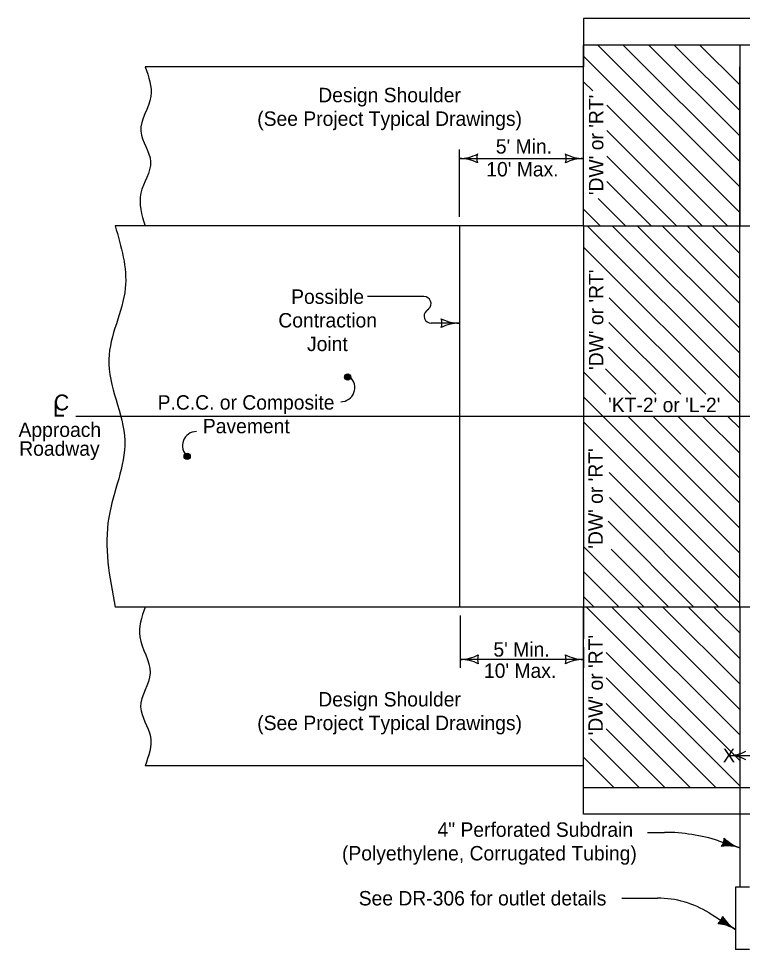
# Model space of a CAD drawing. Extents: x 10045 to 81668, y 6370 to 11018.
# Drawn here: x 10045 to 10888, y 6421 to 7505 of the extents above; entities that cross this region are included whole.
import ezdxf

# ---------------------------------------------------------------- set-up
doc = ezdxf.new("R2010")
doc.units = 0
for name, color, linetype in [('Alignment', 7, 'Continuous'), ('Default', 7, 'Continuous'), ('dsnStdLineWork', 7, 'Continuous')]:
    doc.layers.add(name, color=color, linetype=linetype)

msp = doc.modelspace()

# ---------------------------------------------------------------- linework, layer by layer
at = {"layer": 'Alignment'}
for p, q in [((10558.7, 7274.2), (10558.7, 7352.6)), ((10558.7, 7274.2), (10558.7, 7352.6)), ((10703.2, 7311.2), (10703.2, 7352.6)), ((10703.2, 7311.2), (10703.2, 7352.6)), ((10558.7, 7342.4), (10703.2, 7342.4)), ((10558.7, 7342.4), (10703.2, 7342.4)), ((10703.2, 7263.9), (10703.2, 6819.8)), ((10703.2, 7263.9), (10703.2, 6819.8)), ((10517.3, 7181.6), (10451.7, 7181.6)), ((10517.3, 7181.6), (10451.7, 7181.6)), ((10521.5, 7166.1), (10522.8, 7167.2)), ((10521.5, 7166.1), (10522.8, 7167.2)), ((10558.4, 7150.5), (10525.7, 7150.5)), ((10558.4, 7150.5), (10525.7, 7150.5)), ((10333.1, 7041.9), (10333.1, 7041.9)), ((10333.1, 7041.9), (10333.1, 7041.9)), ((12067.5, 6819.8), (10703.2, 6819.8)), ((12067.5, 6819.8), (10703.2, 6819.8)), ((10559.6, 6810.2), (10559.6, 6749.3)), ((10559.6, 6810.2), (10559.6, 6749.3)), ((10703.2, 6773.2), (10703.2, 6749.3)), ((10703.2, 6773.2), (10703.2, 6749.3)), ((10703.2, 6758.9), (10559.6, 6758.9)), ((10703.2, 6758.9), (10559.6, 6758.9)), ((10872.2, 6647.1), (10903.5, 6647.1)), ((10872.2, 6647.1), (10903.5, 6647.1)), ((10777.8, 6557.4), (10797.5, 6557.4)), ((10777.8, 6557.4), (10797.5, 6557.4)), ((10747.8, 6480.8), (10789.3, 6480.8)), ((10747.8, 6480.8), (10789.3, 6480.8)), ((10849.4, 6463.6), (10880, 6444.4)), ((10849.4, 6463.6), (10880, 6444.4))]:
    msp.add_line(p, q, dxfattribs=at)
for centre, radius, start, end in [((10517.3, 7173.4), 8.22, 311.3092, 90), ((10517.3, 7173.4), 8.22, 311.3092, 90), ((10525.7, 7158.8), 8.22, 131.309, 270), ((10525.7, 7158.8), 8.22, 131.309, 270), ((10420.4, 7075.4), 16.4, 270, 48.6908), ((10420.4, 7075.4), 16.4, 270, 48.6908), ((10252.4, 7007.9), 16.4, 90, 228.691), ((10252.4, 7007.9), 16.4, 90, 228.691), ((10797.5, 6351.9), 205.6, 72.1406, 90), ((10797.5, 6351.9), 205.6, 72.1406, 90), ((10789.3, 6367.8), 113.1, 57.9168, 90), ((10789.3, 6367.8), 113.1, 57.9168, 90)]:
    msp.add_arc(centre, radius, start, end, dxfattribs=at)
at = {"layer": 'Default'}
msp.add_line((11628.3, 7474.4), (10703.2, 7474.4), dxfattribs=at)
msp.add_line((11628.3, 7474.4), (10703.2, 7474.4), dxfattribs=at)
at = {"layer": 'dsnStdLineWork'}
for p, q in [((11591.3, 7505.2), (10703.2, 7505.2)), ((10703.2, 7505.2), (10703.2, 7448.9)), ((11591.3, 7505.2), (10703.2, 7505.2)), ((10703.2, 7505.2), (10703.2, 7448.9)), ((10703.2, 7263.9), (10703.2, 7474.4)), ((10703.2, 7263.9), (10703.2, 7474.4)), ((10885.1, 7309.1), (10719.8, 7474.4)), ((10885.1, 7309.1), (10719.8, 7474.4)), ((10885.1, 7338.8), (10749.5, 7474.4)), ((10885.1, 7338.8), (10749.5, 7474.4)), ((10885.1, 7368.5), (10779.2, 7474.4)), ((10885.1, 7368.5), (10779.2, 7474.4)), ((10885.1, 7398.2), (10808.9, 7474.4)), ((10885.1, 7398.2), (10808.9, 7474.4)), ((10885.1, 7427.9), (10838.6, 7474.4)), ((10885.1, 7427.9), (10838.6, 7474.4)), ((10885.1, 7474.4), (10885.1, 7263.9)), ((10885.1, 7474.4), (10885.1, 7263.9)), ((10885.1, 7279.4), (10703.2, 7461.3)), ((10885.1, 7279.4), (10703.2, 7461.3)), ((10703.2, 7448.9), (10192.4, 7448.9)), ((10703.2, 7448.9), (10192.4, 7448.9)), ((10703.2, 7263.9), (10703.2, 7448.9)), ((10703.2, 7263.9), (10703.2, 7448.9)), ((10885.1, 7263.9), (10885.1, 7448.9)), ((10885.1, 7263.9), (10885.1, 7448.9)), ((10713.8, 7421), (10703.2, 7431.6)), ((10713.8, 7421), (10703.2, 7431.6)), ((10870.9, 7263.9), (10730.2, 7404.5)), ((10870.9, 7263.9), (10730.2, 7404.5)), ((10841.2, 7263.9), (10730.2, 7374.8)), ((10841.2, 7263.9), (10730.2, 7374.8)), ((10811.5, 7263.9), (10730.2, 7345.1)), ((10811.5, 7263.9), (10730.2, 7345.1)), ((10781.8, 7263.9), (10730.2, 7315.4)), ((10781.8, 7263.9), (10730.2, 7315.4)), ((10703.2, 7263.9), (10703.2, 7300.9)), ((10703.2, 7263.9), (10703.2, 7300.9)), ((10752.1, 7263.9), (10720.3, 7295.6)), ((10752.1, 7263.9), (10720.3, 7295.6)), ((10722.4, 7263.9), (10703.2, 7283.1)), ((10722.4, 7263.9), (10703.2, 7283.1)), ((10703.2, 7263.9), (10157.6, 7263.9)), ((10703.2, 7263.9), (10157.6, 7263.9)), ((10558.7, 7263.9), (10558.7, 6819.8)), ((10558.7, 7263.9), (10558.7, 6819.8)), ((10703.2, 7263.9), (12114.2, 7263.9)), ((10703.2, 7263.9), (12114.2, 7263.9)), ((10885.1, 7086.3), (10707.5, 7263.9)), ((10885.1, 7086.3), (10707.5, 7263.9)), ((10885.1, 7115.4), (10736.6, 7263.9)), ((10885.1, 7115.4), (10736.6, 7263.9)), ((10885.1, 7144.5), (10765.7, 7263.9)), ((10885.1, 7144.5), (10765.7, 7263.9)), ((10885.1, 7173.5), (10794.8, 7263.9)), ((10885.1, 7173.5), (10794.8, 7263.9)), ((10885.1, 7202.6), (10823.8, 7263.9)), ((10885.1, 7202.6), (10823.8, 7263.9)), ((10885.1, 7231.7), (10852.9, 7263.9)), ((10885.1, 7231.7), (10852.9, 7263.9)), ((10885.1, 6819.8), (10885.1, 7263.9)), ((10885.1, 6819.8), (10885.1, 7263.9)), ((10885.1, 7057.2), (10703.2, 7239.2)), ((10885.1, 7057.2), (10703.2, 7239.2)), ((10845.6, 7067.7), (10733.1, 7180.2)), ((10845.6, 7067.7), (10733.1, 7180.2)), ((10520.2, 7164.9), (10521.5, 7166.1)), ((10520.2, 7164.9), (10521.5, 7166.1)), ((10816.5, 7067.7), (10732.8, 7151.4)), ((10816.5, 7067.7), (10732.8, 7151.4)), ((10787.4, 7067.7), (10732.4, 7122.7)), ((10787.4, 7067.7), (10732.4, 7122.7)), ((10729.3, 7067.7), (10703.2, 7093.8)), ((10729.3, 7067.7), (10703.2, 7093.8)), ((10758.3, 7067.7), (10728.8, 7097.3)), ((10758.3, 7067.7), (10728.8, 7097.3)), ((10885.1, 6882.8), (10703.2, 7064.7)), ((10885.1, 6882.8), (10703.2, 7064.7)), ((11628.3, 7041.9), (10112, 7041.9)), ((11628.3, 7041.9), (10112, 7041.9)), ((10885.1, 6853.7), (10703.2, 7035.7)), ((10885.1, 6853.7), (10703.2, 7035.7)), ((10885.1, 6911.9), (10755.1, 7041.9)), ((10885.1, 6911.9), (10755.1, 7041.9)), ((10885.1, 6940.9), (10784.2, 7041.9)), ((10885.1, 6940.9), (10784.2, 7041.9)), ((10885.1, 6970), (10813.3, 7041.9)), ((10885.1, 6970), (10813.3, 7041.9)), ((10885.1, 6999.1), (10842.3, 7041.9)), ((10885.1, 6999.1), (10842.3, 7041.9)), ((10885.1, 7028.2), (10871.4, 7041.9)), ((10885.1, 7028.2), (10871.4, 7041.9)), ((10885.1, 6824.6), (10733.1, 6976.6)), ((10885.1, 6824.6), (10733.1, 6976.6)), ((10860.9, 6819.8), (10733.4, 6947.3)), ((10860.9, 6819.8), (10733.4, 6947.3)), ((10831.8, 6819.8), (10731.7, 6919.9)), ((10831.8, 6819.8), (10731.7, 6919.9)), ((10773.6, 6819.8), (10703.2, 6890.3)), ((10773.6, 6819.8), (10703.2, 6890.3)), ((10802.7, 6819.8), (10735.3, 6887.2)), ((10802.7, 6819.8), (10735.3, 6887.2)), ((10744.6, 6819.8), (10703.2, 6861.2)), ((10744.6, 6819.8), (10703.2, 6861.2)), ((10715.5, 6819.8), (10703.2, 6832.1)), ((10715.5, 6819.8), (10703.2, 6832.1)), ((10703.2, 6819.8), (10157.6, 6819.8)), ((10703.2, 6819.8), (10157.6, 6819.8)), ((10703.2, 6819.8), (10703.2, 6782.8)), ((10703.2, 6634.8), (10703.2, 6819.8)), ((10703.2, 6609.3), (10703.2, 6819.8)), ((10703.2, 6819.8), (10703.2, 6782.8)), ((10703.2, 6634.8), (10703.2, 6819.8)), ((10703.2, 6609.3), (10703.2, 6819.8)), ((10885.1, 6641.2), (10706.5, 6819.8)), ((10885.1, 6641.2), (10706.5, 6819.8)), ((10885.1, 6670.9), (10736.2, 6819.8)), ((10885.1, 6670.9), (10736.2, 6819.8)), ((10885.1, 6700.6), (10765.9, 6819.8)), ((10885.1, 6700.6), (10765.9, 6819.8)), ((10885.1, 6730.3), (10795.6, 6819.8)), ((10885.1, 6730.3), (10795.6, 6819.8)), ((10885.1, 6760), (10825.3, 6819.8)), ((10885.1, 6760), (10825.3, 6819.8)), ((10885.1, 6789.7), (10855, 6819.8)), ((10885.1, 6789.7), (10855, 6819.8)), ((10885.1, 6819.4), (10884.7, 6819.8)), ((10885.1, 6819.4), (10884.7, 6819.8)), ((10885.1, 6819.8), (10885.1, 6609.3)), ((10885.1, 6819.8), (10885.1, 6609.3)), ((10885.1, 6611.5), (10729.6, 6767)), ((10885.1, 6611.5), (10729.6, 6767)), ((10857.6, 6609.3), (10729.6, 6737.3)), ((10857.6, 6609.3), (10729.6, 6737.3)), ((10827.9, 6609.3), (10729.6, 6707.6)), ((10827.9, 6609.3), (10729.6, 6707.6)), ((10798.2, 6609.3), (10729.6, 6677.9)), ((10798.2, 6609.3), (10729.6, 6677.9)), ((10768.5, 6609.3), (10711.3, 6666.5)), ((10768.5, 6609.3), (10711.3, 6666.5)), ((10738.8, 6609.3), (10703.2, 6645)), ((10738.8, 6609.3), (10703.2, 6645)), ((10703.2, 6634.8), (10192.4, 6634.8)), ((10703.2, 6634.8), (10192.4, 6634.8)), ((10703.2, 6578.5), (10703.2, 6634.8)), ((10703.2, 6578.5), (10703.2, 6634.8)), ((11628.3, 6609.3), (10703.2, 6609.3)), ((11628.3, 6609.3), (10703.2, 6609.3)), ((10885.1, 6609.3), (10885.1, 6493.6)), ((10885.1, 6609.3), (10885.1, 6493.6)), ((11591.3, 6578.5), (10703.2, 6578.5)), ((11591.3, 6578.5), (10703.2, 6578.5)), ((10860.5, 6547.5), (10885.1, 6539.6)), ((10860.5, 6547.5), (10885.1, 6539.6)), ((10885.1, 6539.6), (10866.3, 6545.7)), ((10885.1, 6539.6), (10866.3, 6545.7)), ((10896.4, 6493.6), (10880, 6493.6)), ((10880, 6493.6), (10880, 6421.2)), ((10896.4, 6493.6), (10880, 6493.6)), ((10880, 6493.6), (10880, 6421.2)), ((10880, 6444.4), (10863.2, 6454.9)), ((10880, 6444.4), (10863.2, 6454.9)), ((10896.4, 6421.2), (10880, 6421.2)), ((10896.4, 6421.2), (10880, 6421.2))]:
    msp.add_line(p, q, dxfattribs=at)
for points in [[(10885.1, 7263.9), (10885.1, 7263.9)], [(10885.1, 7263.9), (10885.1, 7263.9)], [(10428.8, 7084.5), (10427.6, 7085), (10425.7, 7085.6), (10425.4, 7087.5), (10425.6, 7089.2), (10426.8, 7090.8), (10428.6, 7090.6), (10430.5, 7090.4), (10431.4, 7088.8), (10431.6, 7087.3), (10430.5, 7085.2), (10429.1, 7085), (10427.2, 7085.5), (10425.7, 7086.7), (10425.7, 7088.5), (10426.9, 7089.9), (10428.6, 7090.1), (10430.5, 7089.7), (10430.8, 7088.7), (10431.2, 7087.4), (10430.3, 7085.8), (10428.9, 7085.9), (10427.3, 7086.1), (10426.2, 7087), (10426.8, 7088.6), (10428, 7089.5), (10429.5, 7089.5), (10429.9, 7088.7), (10430.4, 7087.7), (10429.7, 7086.5), (10428.5, 7086.2), (10427.5, 7086.7), (10427.4, 7087.9), (10427.9, 7088.7), (10429, 7089), (10429.5, 7088.6), (10429.8, 7087.9), (10429.3, 7087), (10428.5, 7086.8), (10427.8, 7087.3), (10427.9, 7087.9), (10428.4, 7088.3), (10429.2, 7088.3), (10429.2, 7087.7), (10428.5, 7087.4)], [(10428.8, 7084.5), (10427.6, 7085), (10425.7, 7085.6), (10425.4, 7087.5), (10425.6, 7089.2), (10426.8, 7090.8), (10428.6, 7090.6), (10430.5, 7090.4), (10431.4, 7088.8), (10431.6, 7087.3), (10430.5, 7085.2), (10429.1, 7085), (10427.2, 7085.5), (10425.7, 7086.7), (10425.7, 7088.5), (10426.9, 7089.9), (10428.6, 7090.1), (10430.5, 7089.7), (10430.8, 7088.7), (10431.2, 7087.4), (10430.3, 7085.8), (10428.9, 7085.9), (10427.3, 7086.1), (10426.2, 7087), (10426.8, 7088.6), (10428, 7089.5), (10429.5, 7089.5), (10429.9, 7088.7), (10430.4, 7087.7), (10429.7, 7086.5), (10428.5, 7086.2), (10427.5, 7086.7), (10427.4, 7087.9), (10427.9, 7088.7), (10429, 7089), (10429.5, 7088.6), (10429.8, 7087.9), (10429.3, 7087), (10428.5, 7086.8), (10427.8, 7087.3), (10427.9, 7087.9), (10428.4, 7088.3), (10429.2, 7088.3), (10429.2, 7087.7), (10428.5, 7087.4)], [(10241.8, 6992.2), (10240.6, 6992.8), (10238.7, 6993.4), (10238.3, 6995.3), (10238.6, 6997), (10239.8, 6998.5), (10241.6, 6998.4), (10243.5, 6998.1), (10244.4, 6996.6), (10244.5, 6995), (10243.4, 6992.9), (10242, 6992.7), (10240.2, 6993.2), (10238.6, 6994.4), (10238.6, 6996.2), (10239.9, 6997.7), (10241.6, 6997.8), (10243.4, 6997.5), (10243.7, 6996.4), (10244.1, 6995.1), (10243.2, 6993.5), (10241.9, 6993.6), (10240.3, 6993.8), (10239.1, 6994.7), (10239.7, 6996.3), (10240.9, 6997.2), (10242.5, 6997.3), (10242.9, 6996.4), (10243.4, 6995.5), (10242.6, 6994.2), (10241.4, 6993.9), (10240.4, 6994.5), (10240.3, 6995.6), (10240.9, 6996.5), (10241.9, 6996.8), (10242.5, 6996.3), (10242.8, 6995.7), (10242.2, 6994.7), (10241.5, 6994.6), (10240.7, 6995), (10240.9, 6995.6), (10241.4, 6996), (10242.1, 6996), (10242.1, 6995.5), (10241.5, 6995.2)], [(10241.8, 6992.2), (10240.6, 6992.8), (10238.7, 6993.4), (10238.3, 6995.3), (10238.6, 6997), (10239.8, 6998.5), (10241.6, 6998.4), (10243.5, 6998.1), (10244.4, 6996.6), (10244.5, 6995), (10243.4, 6992.9), (10242, 6992.7), (10240.2, 6993.2), (10238.6, 6994.4), (10238.6, 6996.2), (10239.9, 6997.7), (10241.6, 6997.8), (10243.4, 6997.5), (10243.7, 6996.4), (10244.1, 6995.1), (10243.2, 6993.5), (10241.9, 6993.6), (10240.3, 6993.8), (10239.1, 6994.7), (10239.7, 6996.3), (10240.9, 6997.2), (10242.5, 6997.3), (10242.9, 6996.4), (10243.4, 6995.5), (10242.6, 6994.2), (10241.4, 6993.9), (10240.4, 6994.5), (10240.3, 6995.6), (10240.9, 6996.5), (10241.9, 6996.8), (10242.5, 6996.3), (10242.8, 6995.7), (10242.2, 6994.7), (10241.5, 6994.6), (10240.7, 6995), (10240.9, 6995.6), (10241.4, 6996), (10242.1, 6996), (10242.1, 6995.5), (10241.5, 6995.2)], [(10865.6, 6542.1), (10867.4, 6545.3), (10867.8, 6549.1), (10871.3, 6545.7), (10877.5, 6542.1), (10869.8, 6542.7), (10866.3, 6542.3), (10868, 6545.1), (10868.5, 6547.5), (10870.8, 6545.3), (10874.2, 6543.1), (10869.9, 6543.3), (10867.6, 6543.2), (10869, 6546.1), (10871.3, 6544.1), (10869, 6544.1), (10869.3, 6545.1), (10870.2, 6544.5)], [(10865.6, 6542.1), (10867.4, 6545.3), (10867.8, 6549.1), (10871.3, 6545.7), (10877.5, 6542.1), (10869.8, 6542.7), (10866.3, 6542.3), (10868, 6545.1), (10868.5, 6547.5), (10870.8, 6545.3), (10874.2, 6543.1), (10869.9, 6543.3), (10867.6, 6543.2), (10869, 6546.1), (10871.3, 6544.1), (10869, 6544.1), (10869.3, 6545.1), (10870.2, 6544.5)], [(10861.6, 6451.6), (10864.2, 6454.3), (10865.5, 6457.9), (10868.1, 6453.7), (10873.2, 6448.6), (10865.9, 6451.2), (10862.4, 6451.6), (10864.8, 6453.9), (10865.8, 6456.1), (10867.5, 6453.4), (10870.3, 6450.5), (10866.1, 6451.7), (10863.9, 6452.2), (10865.9, 6454.7), (10867.7, 6452.1), (10865.4, 6452.7), (10866, 6453.6), (10866.7, 6452.8)], [(10861.6, 6451.6), (10864.2, 6454.3), (10865.5, 6457.9), (10868.1, 6453.7), (10873.2, 6448.6), (10865.9, 6451.2), (10862.4, 6451.6), (10864.8, 6453.9), (10865.8, 6456.1), (10867.5, 6453.4), (10870.3, 6450.5), (10866.1, 6451.7), (10863.9, 6452.2), (10865.9, 6454.7), (10867.7, 6452.1), (10865.4, 6452.7), (10866, 6453.6), (10866.7, 6452.8)]]:
    msp.add_lwpolyline(points, dxfattribs=at)
for centre in [(10428.5, 7087.8), (10428.5, 7087.8), (10241.5, 6995.5), (10241.5, 6995.5)]:
    msp.add_circle(centre, 3.6, dxfattribs=at)
for centre, radius, start, end in [((10558.7, 7386.7), 44.4, 270, 298.0725), ((10558.7, 7386.7), 44.4, 270, 298.0725), ((10558.7, 7298), 44.4, 61.9275, 90), ((10558.7, 7298), 44.4, 61.9275, 90), ((10595.9, 7342.4), 17.1, 162.2666, 197.7334), ((10595.9, 7342.4), 17.1, 162.2666, 197.7334), ((10665.9, 7342.4), 17.1, 342.2667, 17.7334), ((10703.2, 7386.7), 44.4, 241.9275, 270), ((10665.9, 7342.4), 17.1, 342.2667, 17.7334), ((10703.2, 7386.7), 44.4, 241.9275, 270), ((10703.2, 7298), 44.4, 90, 118.0725), ((10703.2, 7298), 44.4, 90, 118.0725), ((10521.2, 7150.5), 17.1, 342.2667, 17.7334), ((10558.4, 7194.9), 44.4, 241.9275, 270), ((10521.2, 7150.5), 17.1, 342.2667, 17.7334), ((10558.4, 7194.9), 44.4, 241.9275, 270), ((10558.4, 7106.2), 44.4, 90, 118.0725), ((10558.4, 7106.2), 44.4, 90, 118.0725), ((10559.6, 6803.5), 44.6, 270, 298.0725), ((10559.6, 6803.5), 44.6, 270, 298.0725), ((10597, 6758.9), 17.2, 162.2666, 197.7334), ((10597, 6758.9), 17.2, 162.2666, 197.7334), ((10665.7, 6758.9), 17.2, 342.2667, 17.7334), ((10703.2, 6803.5), 44.6, 241.9275, 270), ((10665.7, 6758.9), 17.2, 342.2667, 17.7334), ((10703.2, 6803.5), 44.6, 241.9275, 270), ((10665.7, 6758.9), 17.2, 342.2667, 17.7334), ((10703.2, 6803.5), 44.6, 241.9275, 270), ((10665.7, 6758.9), 17.2, 342.2667, 17.7334), ((10703.2, 6803.5), 44.6, 241.9275, 270), ((10559.6, 6714.3), 44.6, 61.9275, 90), ((10559.6, 6714.3), 44.6, 61.9275, 90), ((10703.2, 6714.3), 44.6, 90, 118.0725), ((10703.2, 6714.3), 44.6, 90, 118.0725), ((10703.2, 6714.3), 44.6, 90, 118.0725), ((10703.2, 6714.3), 44.6, 90, 118.0725), ((10872.2, 6689.4), 42.3, 270, 298.0725), ((10872.2, 6689.4), 42.3, 270, 298.0725), ((10872.2, 6604.8), 42.3, 61.9275, 90), ((10872.2, 6604.8), 42.3, 61.9275, 90), ((10850.2, 6550.9), 16.9, 324.4082, 359.8749), ((10850.2, 6550.9), 16.9, 324.4082, 359.8749), ((10898.5, 6581.2), 43.7, 224.0691, 252.1415), ((10898.5, 6581.2), 43.7, 224.0691, 252.1415), ((10871.7, 6498), 43.7, 72.1415, 100.214), ((10871.7, 6498), 43.7, 72.1415, 100.214), ((10848.9, 6463.9), 16.9, 310.1825, 345.6492), ((10848.9, 6463.9), 16.9, 310.1825, 345.6492), ((10856.8, 6407.4), 43.7, 57.9159, 85.9884), ((10856.8, 6407.4), 43.7, 57.9159, 85.9884), ((10903.2, 6481.4), 43.7, 209.8434, 237.9159), ((10903.2, 6481.4), 43.7, 209.8434, 237.9159)]:
    msp.add_arc(centre, radius, start, end, dxfattribs=at)
for points in [[(10192.4, 7448.9), (10199.3, 7414.7), (10187.5, 7374), (10198.9, 7338.5), (10187.5, 7301.9), (10192.4, 7263.9)], [(10192.4, 7448.9), (10199.3, 7414.7), (10187.5, 7374), (10198.9, 7338.5), (10187.5, 7301.9), (10192.4, 7263.9)], [(10157.6, 7263.9), (10169.4, 7191.2), (10150.2, 7108.6), (10168.7, 7013.7), (10150.2, 6924.3), (10157.6, 6819.8)], [(10157.6, 7263.9), (10169.4, 7191.2), (10150.2, 7108.6), (10168.7, 7013.7), (10150.2, 6924.3), (10157.6, 6819.8)], [(10192.4, 6819.8), (10186.3, 6785.1), (10198.3, 6743.3), (10187.3, 6703.5), (10198.7, 6669.1), (10192.4, 6634.8)], [(10192.4, 6819.8), (10186.3, 6785.1), (10198.3, 6743.3), (10187.3, 6703.5), (10198.7, 6669.1), (10192.4, 6634.8)]]:
    msp.add_spline(points, degree=3, dxfattribs=at)

# ---------------------------------------------------------------- texts
at = {"layer": 'Alignment'}
for s, height, p in [('Design Shoulder', 16.8, (10394.2, 7407.8)), ('Design Shoulder', 16.8, (10394.2, 7407.8)), ('(See Project Typical Drawings)', 16.8, (10323.1, 7380.3)), ('(See Project Typical Drawings)', 16.8, (10323.1, 7380.3)), ("5' Min.", 16.8, (10601, 7348)), ("5' Min.", 16.8, (10601, 7348)), ("10' Max.", 16.8, (10589.9, 7321.4)), ("10' Max.", 16.8, (10589.9, 7321.4)), ('Possible', 16.8, (10362.6, 7173)), ('Possible', 16.8, (10362.6, 7173)), ('Contraction', 16.8, (10347.7, 7145.5)), ('Contraction', 16.8, (10347.7, 7145.5)), ('Joint', 16.8, (10381.1, 7118)), ('Joint', 16.8, (10381.1, 7118)), ('C', 18.4, (10086.3, 7049)), ('C', 18.4, (10086.3, 7049)), ('L', 18.4, (10085.2, 7041.8)), ('L', 18.4, (10085.2, 7041.8)), ('P.C.C. or Composite', 16.8, (10207.1, 7049.8)), ('P.C.C. or Composite', 16.8, (10207.1, 7049.8)), ("'KT-2' or 'L-2'", 16.8, (10731.8, 7046.9)), ("'KT-2' or 'L-2'", 16.8, (10731.8, 7046.9)), ('Approach', 16.8, (10045.1, 7018)), ('Approach', 16.8, (10045.1, 7018)), ('Pavement', 16.8, (10259.8, 7022.3)), ('Pavement', 16.8, (10259.8, 7022.3)), ('Roadway', 16.8, (10045.9, 6996.1)), ('Roadway', 16.8, (10045.9, 6996.1)), ("5' Min.", 16.8, (10598.2, 6762.2)), ("5' Min.", 16.8, (10598.2, 6762.2)), ("10' Max.", 16.8, (10587.2, 6737.4)), ("10' Max.", 16.8, (10587.2, 6737.4)), ('Design Shoulder', 16.8, (10394.2, 6704.1)), ('Design Shoulder', 16.8, (10394.2, 6704.1)), ('(See Project Typical Drawings)', 16.8, (10323.1, 6676.6)), ('(See Project Typical Drawings)', 16.8, (10323.1, 6676.6)), ('X', 16, (10865.4, 6639.1)), ('X', 16, (10865.4, 6639.1)), ('4" Perforated Subdrain ', 16.8, (10533.1, 6552.3)), ('4" Perforated Subdrain ', 16.8, (10533.1, 6552.3)), ('(Polyethylene, Corrugated Tubing)', 16.8, (10421.8, 6524.8)), ('(Polyethylene, Corrugated Tubing)', 16.8, (10421.8, 6524.8)), ('See DR-306 for outlet details', 16.8, (10441.3, 6472.4)), ('See DR-306 for outlet details', 16.8, (10441.3, 6472.4))]:
    msp.add_text(s, height=height, dxfattribs=at).set_placement(p)
for p in [(10726.2, 7299.6), (10726.2, 7299.6), (10726.2, 7096), (10726.2, 7096), (10725.6, 6887.8), (10725.6, 6887.8), (10725.6, 6670.5), (10725.6, 6670.5)]:
    msp.add_text("'DW' or 'RT'", height=16.8, rotation=90, dxfattribs=at).set_placement(p)

doc.saveas('drawing.dxf')
